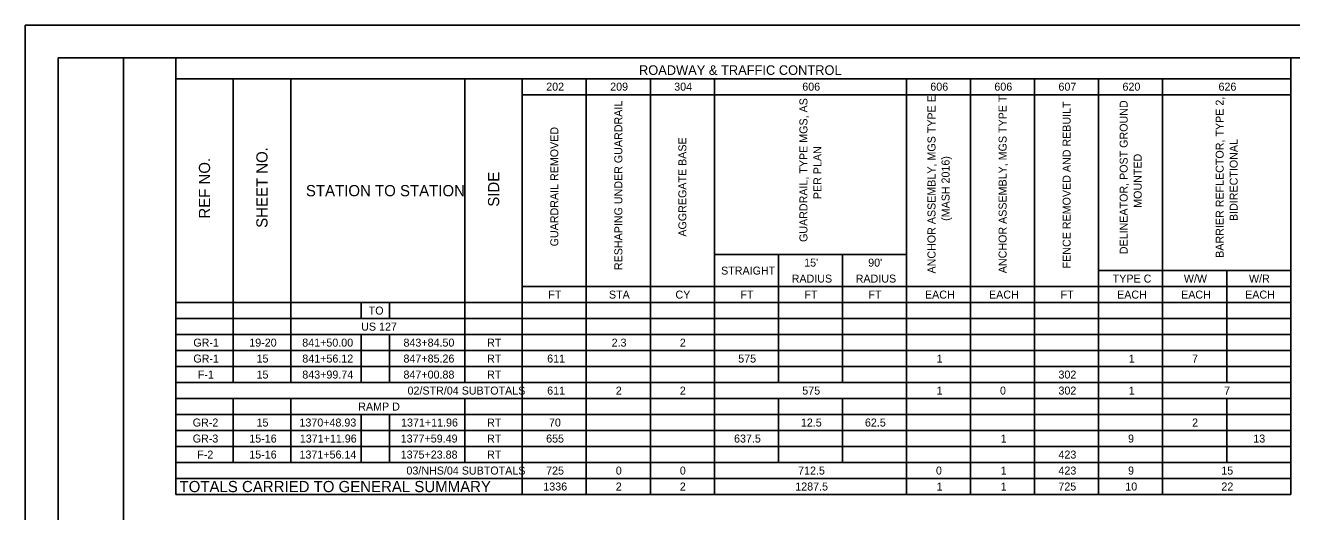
# Model space of a CAD drawing. Extents: x 0 to 34, y 0 to 22.
# Drawn here: x 0 to 19.36, y 14.56 to 22 of the extents above; entities that cross this region are included whole.
import ezdxf

# ---------------------------------------------------------------- set-up
doc = ezdxf.new("R2010")
doc.units = 0
for name, color, linetype in [('Default', 7, 'Continuous'), ('SH_Border', 7, 'Continuous'), ('SH_Cut_Line', 7, 'Continuous')]:
    doc.layers.add(name, color=color, linetype=linetype)

msp = doc.modelspace()

# ---------------------------------------------------------------- linework, layer by layer
at = {"layer": 'Default'}
for p, q in [((2.3, 21.5), (19.347, 21.5)), ((2.3, 21.5), (2.3, 14.819)), ((19.347, 21.5), (19.347, 14.819)), ((2.3, 21.183), (19.347, 21.183)), ((3.178, 21.183), (3.178, 16.533)), ((4.057, 21.183), (4.057, 16.533)), ((6.72, 21.183), (6.72, 16.533)), ((7.598, 21.183), (7.598, 14.819)), ((8.577, 21.183), (8.577, 14.819)), ((9.557, 21.183), (9.557, 14.819)), ((10.536, 21.183), (10.536, 14.819)), ((13.473, 21.183), (13.473, 14.819)), ((14.452, 21.183), (14.452, 14.819)), ((15.431, 21.183), (15.431, 14.819)), ((16.41, 21.183), (16.41, 14.819)), ((17.389, 21.183), (17.389, 14.819)), ((7.598, 20.938), (19.347, 20.938)), ((10.536, 18.491), (13.473, 18.491)), ((11.515, 18.491), (11.515, 16.533)), ((12.494, 18.491), (12.494, 16.533)), ((16.41, 18.246), (19.347, 18.246)), ((18.368, 18.246), (18.368, 16.533)), ((7.598, 18.001), (19.347, 18.001)), ((2.3, 17.757), (19.347, 17.757)), ((5.136, 17.757), (5.136, 17.512)), ((5.568, 17.757), (5.568, 17.512)), ((2.3, 17.512), (19.347, 17.512)), ((2.3, 17.267), (19.347, 17.267)), ((5.136, 17.267), (5.136, 16.533)), ((5.568, 17.267), (5.568, 16.533)), ((2.3, 17.022), (19.347, 17.022)), ((2.3, 16.778), (19.347, 16.778)), ((2.3, 16.533), (19.347, 16.533)), ((2.3, 16.288), (19.347, 16.288)), ((3.178, 16.288), (3.178, 15.309)), ((4.057, 16.288), (4.057, 15.309)), ((6.72, 16.288), (6.72, 15.309)), ((11.515, 16.288), (11.515, 15.309)), ((12.494, 16.288), (12.494, 15.309)), ((18.368, 16.288), (18.368, 15.309)), ((2.3, 16.043), (19.347, 16.043)), ((5.136, 16.043), (5.136, 15.309)), ((5.568, 16.043), (5.568, 15.309)), ((2.3, 15.798), (19.347, 15.798)), ((2.3, 15.554), (19.347, 15.554)), ((2.3, 15.309), (19.347, 15.309)), ((2.3, 15.064), (19.347, 15.064)), ((2.3, 14.819), (19.347, 14.819))]:
    msp.add_line(p, q, dxfattribs=at)
at = {"layer": 'SH_Border'}
for points in [[(0.5, 21.5), (1.5, 21.5), (1.5, 0.5), (0.5, 0.5)], [(1.5, 21.5), (33.5, 21.5), (33.5, 0.5), (1.5, 0.5)]]:
    msp.add_lwpolyline(points, close=True, dxfattribs=at)
at = {"layer": 'SH_Cut_Line'}
msp.add_lwpolyline([(0, 0), (34, 0), (34, 22), (0, 22)], close=True, dxfattribs=at)

# ---------------------------------------------------------------- texts
at = {"layer": 'Default'}
for s, height, p in [('ROADWAY & TRAFFIC CONTROL', 0.14686, (9.382, 21.241)), ('202', 0.1224, (7.964, 21)), ('209', 0.1224, (8.942, 21)), ('304', 0.1224, (9.921, 21)), ('606', 0.1224, (11.879, 21)), ('606', 0.1224, (13.837, 21)), ('606', 0.1224, (14.816, 21)), ('607', 0.1224, (15.796, 21)), ('620', 0.1224, (16.775, 21)), ('626', 0.1224, (18.243, 21)), ('STATION TO STATION', 0.17133, (4.29, 19.384)), ("15'", 0.1224, (11.908, 18.307)), ("90'", 0.1224, (12.887, 18.307)), ('STRAIGHT', 0.1224, (10.638, 18.185)), ('RADIUS', 0.1224, (11.717, 18.063)), ('RADIUS', 0.1224, (12.696, 18.063)), ('TYPE C', 0.1224, (16.625, 18.063)), ('W/W', 0.1224, (17.713, 18.063)), ('W/R', 0.1224, (18.709, 18.063)), ('FT', 0.1224, (7.995, 17.818)), ('STA', 0.1224, (8.923, 17.818)), ('CY', 0.1224, (9.94, 17.818)), ('FT', 0.1224, (10.933, 17.818)), ('FT', 0.1224, (11.912, 17.818)), ('FT', 0.1224, (12.891, 17.818)), ('EACH', 0.1224, (13.755, 17.818)), ('EACH', 0.1224, (14.734, 17.818)), ('FT', 0.1224, (15.828, 17.818)), ('EACH', 0.1224, (16.692, 17.818)), ('EACH', 0.1224, (17.671, 17.818)), ('EACH', 0.1224, (18.65, 17.818)), ('TO', 0.1224, (5.25, 17.573)), ('US 127', 0.1224, (5.135, 17.328)), ('GR-1', 0.1224, (2.569, 17.083)), ('19-20', 0.1224, (3.424, 17.083)), ('841+50.00', 0.1224, (4.234, 17.083)), ('843+84.50', 0.1224, (5.782, 17.083)), ('RT', 0.1224, (7.06, 17.083)), ('2.3', 0.1224, (8.964, 17.083)), ('2', 0.122, (10.007, 17.083)), ('GR-1', 0.1224, (2.569, 16.839)), ('15', 0.1224, (3.535, 16.839)), ('841+56.12', 0.1224, (4.235, 16.839)), ('847+85.26', 0.1224, (5.782, 16.839)), ('RT', 0.1224, (7.06, 16.839)), ('611', 0.1224, (7.979, 16.839)), ('575', 0.1224, (10.9, 16.839)), ('1', 0.122, (13.934, 16.839)), ('1', 0.122, (16.871, 16.839)), ('7', 0.122, (17.839, 16.839)), ('F-1', 0.1224, (2.638, 16.594)), ('15', 0.1224, (3.535, 16.594)), ('843+99.74', 0.1224, (4.235, 16.594)), ('847+00.88', 0.1224, (5.782, 16.594)), ('RT', 0.1224, (7.06, 16.594)), ('302', 0.1224, (15.796, 16.594)), ('02/STR/04 SUBTOTALS', 0.12238, (5.844, 16.349)), ('611', 0.1224, (7.979, 16.349)), ('2', 0.122, (9.028, 16.349)), ('2', 0.122, (10.007, 16.349)), ('575', 0.1224, (11.879, 16.349)), ('1', 0.122, (13.934, 16.349)), ('0', 0.122, (14.902, 16.349)), ('302', 0.1224, (15.796, 16.349)), ('1', 0.122, (16.871, 16.349)), ('7', 0.122, (18.329, 16.349)), ('RAMP D', 0.1224, (5.09, 16.104)), ('GR-2', 0.1224, (2.559, 15.86)), ('15', 0.1224, (3.535, 15.86)), ('1370+48.93', 0.1224, (4.191, 15.86)), ('1371+11.96', 0.1224, (5.745, 15.86)), ('RT', 0.1224, (7.06, 15.86)), ('70', 0.1224, (8.006, 15.86)), ('12.5', 0.1224, (11.858, 15.86)), ('62.5', 0.1224, (12.837, 15.86)), ('2', 0.122, (17.84, 15.86)), ('GR-3', 0.1224, (2.559, 15.615)), ('15-16', 0.1224, (3.424, 15.615)), ('1371+11.96', 0.1224, (4.197, 15.615)), ('1377+59.49', 0.1224, (5.739, 15.615)), ('RT', 0.1224, (7.06, 15.615)), ('655', 0.1224, (7.963, 15.615)), ('637.5', 0.1224, (10.836, 15.615)), ('1', 0.122, (14.913, 15.615)), ('9', 0.122, (16.86, 15.615)), ('13', 0.1224, (18.775, 15.615)), ('F-2', 0.1224, (2.628, 15.37)), ('15-16', 0.1224, (3.424, 15.37)), ('1371+56.14', 0.1224, (4.192, 15.37)), ('1375+23.88', 0.1224, (5.739, 15.37)), ('RT', 0.1224, (7.06, 15.37)), ('423', 0.1224, (15.796, 15.37)), ('03/NHS/04 SUBTOTALS', 0.12238, (5.827, 15.125)), ('725', 0.1224, (7.963, 15.125)), ('0', 0.122, (9.028, 15.125)), ('0', 0.122, (10.007, 15.125)), ('712.5', 0.1224, (11.815, 15.125)), ('0', 0.122, (13.923, 15.125)), ('1', 0.122, (14.913, 15.125)), ('423', 0.1224, (15.796, 15.125)), ('9', 0.122, (16.86, 15.125)), ('15', 0.1224, (18.286, 15.125)), ('TOTALS CARRIED TO GENERAL SUMMARY', 0.17133, (2.358, 14.856)), ('1336', 0.1224, (7.92, 14.881)), ('2', 0.122, (9.028, 14.881)), ('2', 0.122, (10.007, 14.881)), ('1287.5', 0.1224, (11.772, 14.881)), ('1', 0.122, (13.934, 14.881)), ('1', 0.122, (14.913, 14.881)), ('725', 0.1224, (15.795, 14.881)), ('10', 0.1224, (16.818, 14.881)), ('22', 0.1224, (18.287, 14.881))]:
    msp.add_text(s, height=height, dxfattribs=at).set_placement(p)
for s, height, p in [('ANCHOR ASSEMBLY, MGS TYPE E ', 0.12238, (13.916, 18.202)), ('ANCHOR ASSEMBLY, MGS TYPE T', 0.12238, (15.003, 18.206)), ('RESHAPING UNDER GUARDRAIL', 0.12238, (9.128, 18.254)), ('GUARDRAIL, TYPE MGS, AS ', 0.12238, (11.958, 18.684)), ('FENCE REMOVED AND REBUILT', 0.12238, (15.982, 18.28)), ('DELINEATOR, POST GROUND ', 0.12238, (16.854, 18.497)), ('BARRIER REFLECTOR, TYPE 2, ', 0.12238, (18.322, 18.442)), ('GUARDRAIL REMOVED', 0.12238, (8.149, 18.617)), ('AGGREGATE BASE', 0.12238, (10.107, 18.766)), ('PER PLAN', 0.1224, (12.172, 19.34)), ('BIDIRECTIONAL', 0.12238, (18.536, 19.005)), ('REF NO.', 0.1713, (2.825, 19.042)), ('SHEET NO.', 0.1713, (3.703, 18.901)), ('(MASH 2016)', 0.12238, (14.131, 19.007)), ('MOUNTED', 0.1224, (17.068, 19.207)), ('SIDE', 0.1713, (7.245, 19.224))]:
    msp.add_text(s, height=height, rotation=90, dxfattribs=at).set_placement(p)

doc.saveas('drawing.dxf')
